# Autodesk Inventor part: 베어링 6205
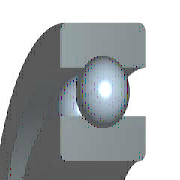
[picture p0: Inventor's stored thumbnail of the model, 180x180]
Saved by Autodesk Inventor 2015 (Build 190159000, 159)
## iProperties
Created: 2015-10
Part Number: 베어링 6205
Material: Steel, Mild
Description: 깊은 그루브 볼 베어링
Document SubType Name: Modeling
Standard: KS B 2023
Designer: mdu
Standards Organization: KS
Language: ko-KR
Size Designation: 6205 - 25 x 52 x 15
Categories: <MemberInstance><Categories><Category DisplayName="샤프트 부품" InternalName="7f7aeb1f-a693-4053-b835-cee3144e0d98" Mnemonic="SHFT"><Category DisplayName="베어링" Inter
Density: 7.85 g/cm^3
Appearance: Steel
Mass: 129.378 g
Surface Area: 107.326 cm^2
Volume: 16.4813 cm^3
IsCustomPart: 1
Author: mdu
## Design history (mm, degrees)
revolve "본체" stored, may be unused: angle "d6" = 90 deg
revolve "볼" stored, may be unused: angle "d7" = 90 deg
pattern_circular "IDS_ARRAYBALL[SIMPL:T]" dims angle "d3" = 360 deg
body "Solid1"
sketch "스케치" dims "d0" = 7.02 (= -0.26 x WD + 0.26 x BD)
  geometry: L1 (3.99, 19.25)-(11.01, 19.25); L2 (7.5, 19.25)-(7.5, 15.74); L3 (7.5, 19.25)-(7.5, 22.76); L4 (4.892, 16.901)-(0, 16.901); L5 (0, 12.5)-(15, 12.5); L6 (4.892, 21.599)-(0, 21.599); L7 (0, 26)-(15, 26); L8 (15, 12.5)-(15, 16.901); L9 (10.108, 16.901)-(15, 16.901); L10 (10.108, 21.599)-(15, 21.599); L11 (15, 26)-(15, 21.599); L12 (-1.4, 0)-(8.4, 0) reference; L13 (0, -0.3)-(0, 5.3) reference
  constraints: 22 end point, 4 point on line, 2 collinear, 2 perpendicular, 2 symmetric about line, 1 midpoint, 1 parallel, 14 other
  dimensions: "d9" = 25 diameter of L5 L12 (= WD); "d11" = 52 diameter of L7 L12 (= BD); "d12" = 15 distance between parallel lines of L8 L13 (= KB); "d13" = 33.802 diameter of L9 L12 (= 0.326 x BD + 0.674 x WD)
fillet "모깎기1" dims "d1" = 1 (= KRS)
other parameters: "WD" = 25 [user parameter; used in 5 equation terms], "BD" = 52 [user parameter; used in 5 equation terms], "KB" = 15 [user parameter; used in 1 equation term], "KRS" = 1 [user parameter; used in 1 equation term], "d4" = 0, "d5" = 0, "d8" = 0, "d14" = 0, "d15" = 0, "BBA" = 0 [user parameter], "BC0" = 7800000 [user parameter], "BC" = 1.4e+07 [user parameter], "BR" = 26 (= 0.5 x BD) [user parameter], "WR" = 12.5 (= 0.5 x WD) [user parameter]
